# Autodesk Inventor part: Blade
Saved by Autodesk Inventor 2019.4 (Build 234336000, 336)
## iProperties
Created: 2020-04
Part Number: Blade
Material: Generic
Document SubType Name: Modeling
Designer: Administrator
Density: 1 g/cm^3
Appearance: Default
Title: Blade v3
Author: Administrator
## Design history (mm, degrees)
feature "Body1"
body "Solid1"
